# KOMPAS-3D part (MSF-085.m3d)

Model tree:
1. Ось X
2. Ось Y
3. Ось Z
4. Начало координат  (labels: Операция без истории:1)

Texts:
  Линия-выноска #1
  Линия-выноска #2
  Линия-выноска #3
  Отклонения формы и база
  Марка координационной оси
  Марка/позиционное обозначение с линией-выноской
  Марка/позиционное обозначение на линии
  Марка/позиционное обозначение без линии-выноски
